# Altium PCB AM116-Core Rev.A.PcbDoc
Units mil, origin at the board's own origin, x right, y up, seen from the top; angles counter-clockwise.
Board outline 2542.62 x 1642.92 mil, 2 copper layers (Top Layer, Bottom Layer); 68 components, 59 nets, 273 pads, 217 vias.
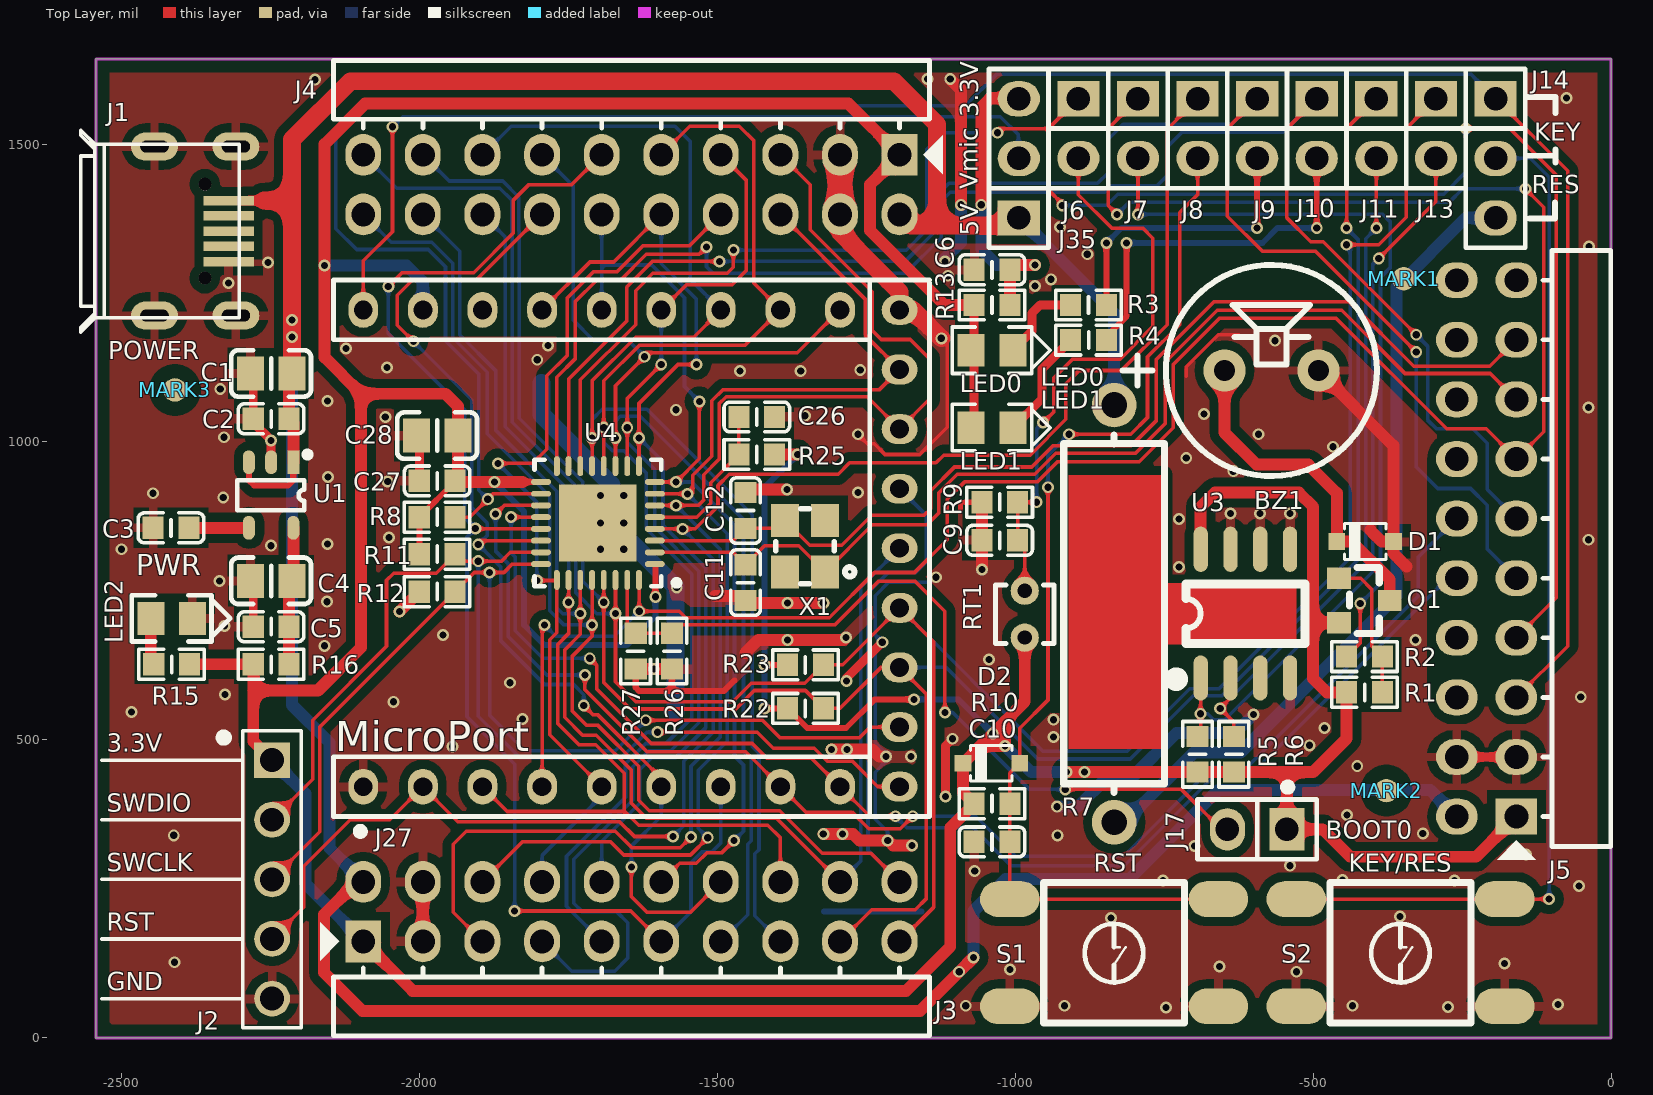
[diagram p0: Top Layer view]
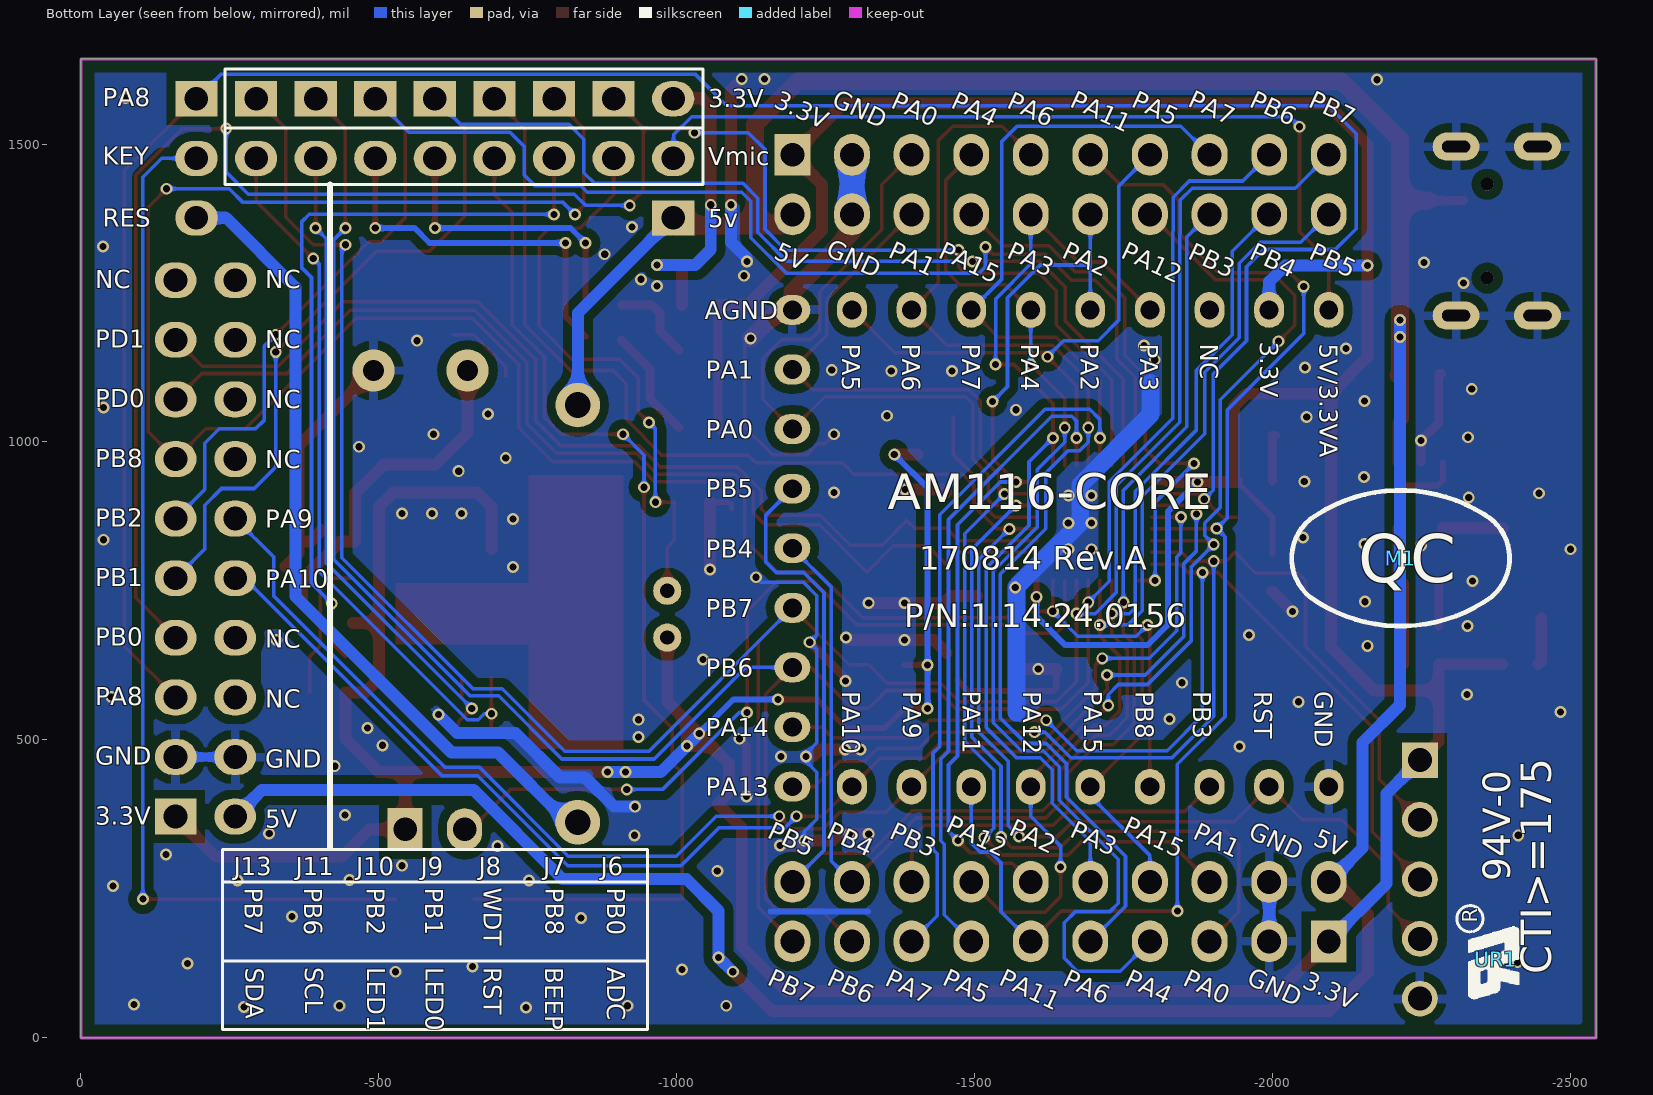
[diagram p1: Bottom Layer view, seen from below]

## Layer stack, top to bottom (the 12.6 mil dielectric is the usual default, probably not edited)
Top Solder: solder mask 0.4, Solder Resist, Dk 3.5
Top Layer: signal copper 1.4
Dielectric1: core 12.6, FR-4, Dk 4.8
Bottom Layer: signal copper 1.4
Bottom Solder: solder mask 0.4, Solder Resist, Dk 3.5

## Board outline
-2542.62,0 0,0 0,1642.92 -2542.62,1642.92

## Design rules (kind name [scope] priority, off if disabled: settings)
Clearance Clearance_Keepout [OnLayer('Keep-Out Layer')] p1: gap=20
Clearance Clearance_Manual [OnLayer('Bottom Layer') and IsSMTPin vs IsPadHoleValid>   (  HasFootprint('PAD-35/50') or   HasFootprint('HOLE-3.2') or  HasFootprint('HOLE-3.2 - Screw') or   HasFootprint('HOLE4.22-SMT') or   HasFootprint('Mou Hole-300D450W310H-SMD') or    HasFootprint('AW6748') or  HasFootprint('IDCS80P500W-20X2-F')  )] p2: gap=50
Clearance Clearance_Via2Via [IsVia vs IsVia] p3: gap=6
Clearance Clearance_Poly2All [InPoly] p4: gap=15
Clearance Clearance_TP [HasFootprint('PAD-40') vs HasFootprint('PAD-40')] p5: gap=50
Clearance [All] p6: gap=6
ComponentClearance [All] p1: gap=0 collisioncheckmode=3 verticalgap=0 showdistances=FALSE
DiffPairsRouting [All] p1: maxlimit=8 minlimit=8 mostfreqgap=8 toplayer_minwidth=5.5 toplayer_maxwidth=5.5 toplayer_prefwidth=5.5 bottomlayer_minwidth=5.5 bottomlayer_maxwidth=5.5 bottomlayer_prefwidth=5.5 maxuncoupledlength=500
HoleSize [All] p1: absolutevalues=TRUE maxlimit=1000 minlimit=1 maxpercent=80.000 minpercent=20.000
MinimumSolderMaskSliver [All] p1: minsoldermaskwidth=1
PlaneClearance PlaneClearance_Full [IsVia] p1: clearance=9
PlaneClearance [All] p2: clearance=20
PlaneConnect PlaneConnect_Full [IsVia] p1: planeconnectstyle=Direct reliefexpansion=20 reliefentries=4 reliefconductorwidth=10 reliefairgap=10
PlaneConnect [All] p2: planeconnectstyle=Relief reliefexpansion=10 reliefentries=4 reliefconductorwidth=15 reliefairgap=10
PolygonConnect PolygonConnect_SMDHole [HasFootprint('Mou Hole-300D450W310H-SMD') or HasFootprint('Mou Hole-373D600H-SMD')] p1: connectstyle=Relief reliefconductorwidth=80 reliefentries=4 polygonreliefangle="45 Angle" airgapwidth=20
PolygonConnect PolygonConnect_Full [IsVia or   HasFootprint('PAD-40') or   HasFootprint('PAD-35/50') or  HasFootprint('HOLE-3.2') or   HasFootprint('HOLE-3.2 - Screw')] p2: connectstyle=Direct reliefconductorwidth=10 reliefentries=4 polygonreliefangle="90 Angle" airgapwidth=10
PolygonConnect [All] p3: connectstyle=Relief reliefconductorwidth=15 reliefentries=4 polygonreliefangle="90 Angle" airgapwidth=15
RoutingVias [All] p1: holewidth=12 width=20 viastyle="Through Hole" minholewidth=12 minwidth=20 maxholewidth=12 maxwidth=20
SilkToSilkClearance [All] p1: silktosilkclearance=0
SilkToSolderMaskClearance [IsPad] p1: minsilkscreentomaskgap=0 clearancetoexposedcopper=TRUE
SolderMaskExpansion [All] p1: expansion=4
Width [All] p1: maxlimit=100 minlimit=6 preferedwidth=6
22 further rules are at their usual default settings.

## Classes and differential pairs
component class U_02A: C1 C2 C3 C4 C5 LED2 R15 R16 U1
component class U_03: BZ1 C9 D1 J6 J7 J9 J10 J11 J13 J14 LED0 LED1 Q1 R1 R2 R3 R4 R5 R6 R7 R8 R9 RT1 S2 U3
component class U_08: C10 C11 C12 C26 C27 C28 D2 J2 J8 J17 R10 R11 R12 R22 R23 R25 R26 R27 S1 U4 X1
component class U_05: J3 J4 J5
component class 01.Main: C6 M1 MARK1 MARK2 MARK3 R13 UR1
component class U_04: J27 J35
component class U_07: J1

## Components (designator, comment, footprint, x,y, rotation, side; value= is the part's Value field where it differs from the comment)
BZ1 "BUZZER2" BUZZ-4/9 -570,1120 r0 top locked
C1 "106" 0805C -2248.62,1115 r180 top
C2 "105" 0603C -2248.62,1039 r180 top
C3 "103" 0603C -2416.62,856 r180 top
C4 "475" 0805C -2248.62,767 r180 top
C5 "104,±10%" 0603C -2248.62,690 r180 top
C6 "4.7uF" 0603C -1039,1289 r0 top
C9 "472,±10%" 0603C -1026,834.97 r180 top
C10 "105,1μF" 0603C -1039,328.97 r180 top
C11 "22P,±5%" 0603C -1452.64,764 r270 top
C12 "22P,±5%" 0603C -1452.64,885 r90 top
C26 "4.7uF" 0603C -1433.64,1042 r0 top
C27 "104,±10%" 0603C -1970,934.78 r180 top
C28 "106" 0805C -1970,1010.78 r180 top
D1 "DIODE1" SOD-323 -412.76,832.9 r180 top
D2 "DIODE1" SOD-323 -1040,460.97 r180 top
J1 "A01SB141B1-261,MicroUSB插座" MICROUSB-5S -2529,1353.92 r270 top locked
J2 "SWD" SIP-5-2.54-R90 -2247,266.05 r90 top
J3 "HEADER 10X2" IDC-20-2.54-R90 -1644,211.92 r0 top locked
J4 "HEADER 10X2" IDC-20-2.54-R90 -1644,1431.92 r180 top locked
J5 "HEADER 10X2" IDC-20-2.54-R90 -209,821.42 r90 top locked
J6 "CON2" SIP-2-2.54 -894,1525.97 r270 top locked
J7 "CON2" SIP-2-2.54 -794,1525.97 r270 top locked
J8 "RST" SIP-2-2.54 -694,1525.98 r270 top locked
J9 "CON2" SIP-2-2.54 -594,1525.97 r270 top locked
J10 "CON2" SIP-2-2.54 -494,1525.98 r270 top locked
J11 "CON2" SIP-2-2.54 -394,1525.98 r270 top locked
J13 "CON2" SIP-2-2.54 -294,1525.98 r270 top locked
J14 "CON3" SIP-3-2.54 -194,1475.98 r270 top locked
J17 "BOOT0" SIP-2-2.54 -594,350 r180 top locked
J27 "3X7Inter" "SIP-27 2.54C" -1988.98,321.66 r90 top locked
J35 "Vol_Sel" SIP-3-2.54 -994,1475.97 r90 top locked
LED0 "LED1" LED-0805 -1039,1154 r0 top
LED1 "LED1" LED-0805 -1039,1024 r0 top
LED2 "LED1" LED-0805 -2415.62,704 r0 top
M1 "ZY QC" ZY_QC -2214.74,804.97 r180 bottom
MARK1 "MARKER" MARKER-C-1.0M -348,1274 r0 top
MARK2 "MARKER" MARKER-C-1.0M -377,415 r90 top
MARK3 "MARKER" MARKER-C-1.0M -2409.98,1087.31 r90 top
Q1 "PNP-1" SOT-23 -414,734 r0 top
R1 "10KΩ,±1%" 0603R -413.76,579.89 r180 top
R2 "1.5KΩ" 0603R -413.76,639.9 r0 top
R3 "1.5KΩ" 0603R -877,1230 r0 top
R4 "1.5KΩ" 0603R -876.9,1171 r0 top
R5 "10KΩ,±1%" 0603R -694,476 r270 top
R6 "10KΩ,±1%" 0603R -633,476 r270 top
R7 "20Ω,±5%" RESAD1778W80L1450D430P -833.95,711.9 r270 top locked
R8 "4.7KΩ" 0603R -1970,873.78 r180 top
R9 "2KΩ,±0.5%" 0603R -1026,898.97 r180 top
R10 "10kΩ" 0603R -1039,392.97 r180 top
R11 "10kΩ" 0603R -1970,811.78 r180 top
R12 "10kΩ" 0603R -1970,748.78 r0 top
R13 "10Ω" 0603R -1039,1230 r180 top
R15 "1.5kΩ" 0603R -2415.62,627 r180 top
R16 "0Ω" 0603R -2248.62,627 r180 top
R22 "10kΩ" 0603R -1352,553 r180 top
R23 "10kΩ" 0603R -1352,626 r180 top
R25 "10Ω" 0603R -1433.64,979 r0 top
R26 "10kΩ" 0603R -1576,649 r90 top
R27 "10KΩ" 0603R -1637,649 r90 top
RT1 "MF52E-103F3435FB-A(2.5MM)" RES-NTC(2.0) -984,711 r180 top
S1 "RST" KEY-6S -834,142.97 r180 top locked
S2 "SW-PB4P" KEY-6S -353.36,142.94 r180 top locked
U1 "CAT6219-330TD" SOT-23-5 -2248.62,911 r270 top
U3 "LM75B" SOIC127P600X175-8N -613.74,712.01 r90 top
U4 "MM32L061NTTR" QFN50P500X500X85-33N -1700.26,864.03 r180 top locked
UR1 "UR" ZY_UR-3X2 -2374,132 r90 bottom
X1 "12.0000MHz,±10ppm" XTAL4-3.2X2.5 -1352.64,825 r90 top

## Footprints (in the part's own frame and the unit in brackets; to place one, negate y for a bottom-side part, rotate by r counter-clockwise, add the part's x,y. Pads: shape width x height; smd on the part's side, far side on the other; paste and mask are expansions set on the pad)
0603C [mm]
  rect 0.9x0.95 smd: 1(-0.762,0) 2(0.762,0)
  silkscreen extent -1.4,-0.64 1.4,0.64, body extent -0.79,-0.38 0.81,0.42, height 0.3
0603R [mm]
  rect 0.9x0.95 smd: 1(-0.762,0) 2(0.762,0)
  silkscreen extent -1.4,-0.63 1.4,0.64, body extent -0.8,-0.4 0.8,0.4, height 0.3
0805C [mm]
  rect 1.15x1.45 smd: 1(-0.889,0) 2(0.889,0)
  silkscreen extent -1.7,-0.99 1.7,0.99, body extent -1,-0.63 1,0.63, height 0.78
BUZZ-4/9 [mm]
  round 1.8 hole 0.9: 1(-2,0) 2(2,0)
  silkscreen extent -6.35,-4.5 4.5,4.5
IDC-20-2.54-R90 [mil]
  rect 60x70 hole 40: 1(-450,-50)
  oval 60x70 hole 40: 2(-450,50) 3(-350,-50) 4(-350,50) 5(-250,-50) 6(-250,50) 7(-150,-50) 8(-150,50) 9(-50,-50) 10(-50,50) 11(50,-50) 12(50,50) 13(150,-50) 14(150,50) 15(250,-50) 16(250,50) 17(350,-50) 18(350,50) 19(450,-50) 20(450,50)
  silkscreen extent -522,-208 500,-17
KEY-6S [mil]
  oval 100x60 smd: 1(-175,90) 2(-175,-90) 3(175,-90) 4(175,90)
  silkscreen extent -118,-118 118,118, body extent -201,-122 201,122, height 268
LED-0805 [mm] "130513 缩短焊盘及丝印，和0805电阻一样LSB"
  rect 1.15x1.4 smd: 1(-0.889,0) 2(0.889,0)
  silkscreen extent -1.7,-0.99 2.49,0.99, body extent -1,-0.64 1,0.64, height 1.1
MARKER-C-1.0M [mm]
  round 1 smd paste-1.016 mask+0.5: 0(0,0)
  Top Layer pour cut-out: -1.1,0 -1.016,-0.421 -0.778,-0.778 -0.421,-1.016 0,-1.1 0,-1.1 0.421,-1.016 0.778,-0.778 1.016,-0.421 1.1,0 1.1,0 1.016,0.421 0.778,0.778 0.421,1.016 0,1.1 0,1.1 -0.421,1.016 -0.778,0.778 -1.016,0.421 -1.1,0
MICROUSB-5S [mm]
  oval 1.2x2 on Top Paste: 0(-3.6,2.15) 0(-3.6,5.62) 0(3.6,2.15) 0(3.6,5.62)
  round 0.54 hole 0.55 unplated: 0(-2,4.3) 0(2,4.3)
  rect 0.4x2.15 smd: 1(-1.3,5.31) 2(-0.65,5.31) 3(0,5.31) 4(0.65,5.31) 5(1.3,5.31)
  oval 1.2x2 hole 0.5 slot 1.2 at 90 deg: 6(-3.6,5.62) 7(3.6,5.62) 8(-3.6,2.15) 9(3.6,2.15)
  silkscreen extent -4.3,-0.99 4.3,5.77
QFN50P500X500X85-33N [mm] "QFN, 32-Leads, Body 5.00x5.00mm, Pitch 0.50mm, Thermal Pad 3.60x3.60mm, IPC Medium Density"
  oval 0.85x0.25 smd: 1(-2.425,1.75) 2(-2.425,1.25) 3(-2.425,0.75) 4(-2.425,0.25) 5(-2.425,-0.25) 6(-2.425,-0.75) 7(-2.425,-1.25) 8(-2.425,-1.75) 17(2.425,-1.75) 18(2.425,-1.25) 19(2.425,-0.75) 20(2.425,-0.25) 21(2.425,0.25) 22(2.425,0.75) 23(2.425,1.25) 24(2.425,1.75)
  oval 0.25x0.85 smd: 9(-1.75,-2.425) 10(-1.25,-2.425) 11(-0.75,-2.425) 12(-0.25,-2.425) 13(0.25,-2.425) 14(0.75,-2.425) 15(1.25,-2.425) 16(1.75,-2.425) 25(1.75,2.425) 26(1.25,2.425) 27(0.75,2.425) 28(0.25,2.425) 29(-0.25,2.425) 30(-0.75,2.425) 31(-1.25,2.425) 32(-1.75,2.425)
  rect 3.3x3.3 smd: 33(0,0)
  silkscreen extent -3.47,-2.7 2.7,2.7, body extent -2.55,-2.55 2.55,2.55, height 0.85
RES-NTC(2.0) [mm]
  round 1.2 hole 0.6: 1(0,1) 2(0,-1)
  silkscreen extent -1.25,-1.25 1.25,1.25
RESAD1778W80L1450D430P [mm]
  round 1.9 hole 1.1: 1(-8.89,0) 2(8.89,0)
  silkscreen extent -7.62,-2.15 7.62,2.15
SIP-2-2.54 [mm]
  rect 1.5x1.8 hole 1: 1(-1.27,0)
  oval 1.5x1.8 hole 1: 2(1.27,0)
  silkscreen extent -2.54,-1.27 2.54,1.27, body extent -2.54,-1.27 2.54,1.27, height 7.58
SIP-3-2.54 [mm]
  rect 1.5x1.8 hole 1: 1(-2.54,0)
  oval 1.5x1.8 hole 1: 2(0,0) 3(2.54,0)
  silkscreen extent -3.81,-1.27 3.81,1.27, body extent -3.81,-1.27 3.81,1.27, height 7.58
SIP-5-2.54-R90 [mil]
  rect 60x60 hole 40.16: 1(200,0)
  round 60 hole 40.16: 2(100,0) 3(0,0) 4(-100,0) 5(-200,0)
  silkscreen extent -249,-49 249,285
"SIP-27 2.54C" [mil]
  oval 60x50 hole 31.5: 1(100,105) 2(100,5) 3(100,-95) 4(100,-195) 5(100,-295) 6(100,-395) 7(100,-495) 8(100,-595) 9(100,-695) 19(900,-695) 20(900,-595) 21(900,-495) 22(900,-395) 23(900,-295) 24(900,-195) 25(900,-95) 26(900,5) 27(900,105)
  oval 50x60 hole 31.5: 10(100,-795) 11(200,-795) 12(300,-795) 13(400,-795) 14(500,-795) 15(600,-795) 16(700,-795) 17(800,-795) 18(900,-795)
  silkscreen extent 20,-845 950,155
SOD-323 [mil]
  rect 28x28 smd: 1(-47.5,0) 2(47.5,0)
  silkscreen extent -35,-30 35,30, body extent -51,-26 51,25, height 39
SOIC127P600X175-8N [mil]
  oval 76.06x24 smd: 1(-108.03,75) 2(-108.03,25) 3(-108.03,-25) 4(-108.03,-75) 5(108.03,-75) 6(108.03,-25) 7(108.03,25) 8(108.03,75)
  silkscreen extent -118,-100 50,124, body extent -118,-96 118,97, height 61
SOT-23 [mil]
  rect 40x36 smd: 1(-42.5,37.4) 2(-42.5,-37.4) 3(42.5,0)
  silkscreen extent -25,-55 25,56, body extent -47,-57 50,58, height 39
SOT-23-5 [mil]
  rect 40x20 smd: 1(-55,37.4)
  oval 40x20 smd: 2(-55,0) 3(-55,-37.4) 4(55,-37.4) 5(55,37.4)
  silkscreen extent -73,-57 26,66, body extent -55,-57 55,57, height 43
XTAL4-3.2X2.5 [mm] "3.2x2.5x0.75mm"
  rect 1.4x1.2 smd: 1(-1.1,-0.85) 2(1.1,-0.85) 3(1.1,0.85) 4(-1.1,0.85)
  silkscreen extent -1.6,-2.1 1.6,1.25
ZY_QC [mil]
  silkscreen extent -183,-114 183,114
ZY_UR-3X2 [mil]
  silkscreen extent -67,-40 90,65

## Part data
BZ1: library part 1.06.09.0016, "Buzzer有极性"
C1 C28: library part 1.02.02.0055, "106,10μF,±10%,10V,X5R,0805,RoHS"
C2 C10: library part 1.02.01.0036, "105,1μF,±10%,16V,X7R,0603,*,RoHS"
C3: library part 1.02.01.0024, "103,±10%,50V,X7R,0603,*,RoHS"
C4: library part 1.02.02.0064, "475,±10%,16V,X7R,0805,RoHS"
C5: library part 1.02.01.0032, "Capacitor"
C6 C26: library part 1.02.01.0080, "GRM188R61A475KE15D,4.7uF,±10%,10V,X5R,0603,muRata,RoHS"
C9: library part 1.02.01.0057, "Capacitor"
C11 C12: library part 1.02.01.0005, "22P,±5%,50V,COG,0603,*,RoHS"
C27: library part 1.02.01.0032, "104,±10%,50V,X7R,0603,*,RoHS"
D1 D2: library part 1.04.07.0027, "1N4148,SOD-323,RoHS"
J1: library part 1.10.12.0014, "A01SB141B1-261,MicroUSB插座,SMT,艾立信,RoHS"
J2: library part CON5, "Connector"
J6 J7 J9 J10 J11 J13 J14: "Connector"
J8 J17: library part CON2, "Connector"
J35: library part CON3, "Connector"
LED0 LED1: library part 1.04.05.0002, "绿色,0805,0805,RoHS"
LED2: library part 1.04.05.0001, "红色,0805,0805,RoHS"
Q1: library part 1.04.09.0002, "PNP Transistor"
R1 R5 R6 R10 R11 R12 R22 R23 R26: library part 1.01.01.0052, "10KΩ,±1%,0603,*,RoHS"
R2 R3 R4 R15: library part 1.01.01.0037, "1.5KΩ,0603,*,RoHS"
R7: library part 1.01.10.0003, "20Ω,±5%,2W,Ф5.5×16mm,RoHS"
R8: library part 1.01.01.0045, "4.7KΩ,0603,*,RoHS"
R9: library part 1.01.01.0084
R13 R25: library part 1.01.01.0007, "10Ω,0603,*,RoHS"
R16: library part 1.01.01.0001
R27: library part 1.01.01.0051, "10KΩ,0603,*,RoHS"
RT1: library part 1.01.14.0011, "MF52E-103F3435FB-A(2.5MM),THT,RoHS"
S1 S2: library part 1.09.01.0003, "6×6×5.0mm,黑色,SMD,,*"
U1: library part 1.05.10.0321, "CAT6219-330TD,TSOT-23-5,ON,RoHS"
U3: library part 1.05.10.0602, "LM75BD,SO-9,NXP,RoHS"
U4: library part 1.05.02.0199, "MM32L061NTTR,QFN32,mindmotion,RoHS"
X1: library part 1.07.01.0032, "12.0000MHz,±10ppm,10pF,-40~85℃,±10ppm,SMD3225,*,JYEG,RoHS"

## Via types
v1: diameter 20, hole 12, Top Layer to Bottom Layer, tented both sides, 217 vias

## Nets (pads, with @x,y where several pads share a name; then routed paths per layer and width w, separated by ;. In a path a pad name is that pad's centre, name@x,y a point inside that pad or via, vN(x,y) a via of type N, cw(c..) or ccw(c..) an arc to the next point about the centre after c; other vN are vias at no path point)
3.3V: C27.1 C28.1 D2.2 J2.1 J3.1 J4.1 J5.1 J17.1 J27.26 LED0.1 LED1.1 Q1.2 R1.2 R5.2 R6.2 R8.2 R10.2 R11.2 R13.2 R15.1 R16.2 R22.2 R23.2 R25.2 RT1.1 U3.8 U4.1 U4.17 | length 9438.1
  Top Layer w9: -1826.92,932.92 U4.17@-1796.72,932.92
  Top Layer w10: R11.2 R8.2 -1940,933.78 C27.1 ; -1912.36,932.92 -1910.26,935.03 ; v1(-1603.8,740.2) U4.1@-1603.8,795.13 ; v1(-1421,553) R22.2 -1349,520 -1284,520 -1236,568 v1(-1170,568) ; v1(-1421,626) R23.2
  Top Layer w15: LED1.1@-1074,1019 -1069,1024 R13.2
  Top Layer w20: R15.1 R16.2 ; R16.2 -2278.62,583 ; J2.1 -2278.62,497.67 -2278.62,583 ; J3.1 -2011.08,79 -1183,79 -1109,153 -1109,352.98 R10.2 -1087.5,411.48 D2.2 -1058.47,490 ; -1826.92,932.92 -1912.36,932.92 -1938.14,932.92 C27.1 -1935,939.78 C28.1 -1935,1060 -1956,1081 -2098,1081 ; R25.2 v1(-1365,979) ; R13.2 -1119,1230 -1244,1355 -1244,1431.92 J4.1 -1280.08,1568 -2091,1568 -2159,1500 v1(-2159,1296) -2159,1142 -2098,1081 ; RT1.1 -984,564.47 -1017,531.47 ; v1(-914,446) R5.2 R6.2 -544,446 ; U3.8 -688.74,891.26 -665,915 -524,915 -500,891 -500,696.6 ; Q1.2 -500,696.6 ; J5.1 -226.42,304 -438,304 -484,350 J17.1 -544,446 ; -2278.62,583 -2170,583 -2098,655 -2098,1081 ; -1058.47,490 v1(-1017,490) ; -1058.47,490 v1(-1037.74,510.74) ; v1(-1037.74,510.74) v1(-1017,490) ; v1(-1037.74,510.74) -1017,531.47 ; v1(-1017,490) -1017,531.47 ; -544,446 -500.24,446 -443.76,502.48 R1.2 -476.89,579.89 -500,603 -500,696.6
  Bottom Layer w10: v1(-1874,933) -1824,883 -1824,693 -1790,659 -1652,659 -1603.8,707.2 v1(-1603.8,740.2) ; v1(-1421,553) v1(-1421,626) -1421,923 v1(-1365,979) ; v1(-1170,568) -1095,568 v1(-1037.74,510.74)
  Bottom Layer w20: J2.1 -2191,410.05 -2191,258.92 J3.1 ; v1(-2159,1296) -2021,1296 -1993.98,1268.98 J27.26 ; v1(-1037.74,510.74) -973,446 v1(-914,446) v1(-883.77,446)
3.3VA: C6.2 J35.3 R13.1 | length 512.7
  Top Layer w20: v1(-1057,1398) -1057,1562 -1042,1577 J35.3@-994.62,1577 ; R13.1 C6.2 -1001,1297 v1(-967,1297)
  Bottom Layer w20: v1(-1057,1398) -1057,1323 -1031,1297 v1(-967,1297)
3.3VA_MM32L: C26.1 R25.1 U4.5 | length 267
  Top Layer w6: U4.5@-1603.8,873.87 -1534.13,873.87 -1510.76,897.24 -1510.76,931.88 R25.1 C26.1
5V: C1.1 C2.1 J1.1 J3.2 J4.2 J5.2 J35.1 R7.1 U1.1 U1.3 | length 6081.5
  Top Layer w10: U1.3 -2286.02,936.02 -2277,927 -2220,927 -2211.22,935.78 U1.1
  Top Layer w15: J1.1 -2260.9,1405.1
  Top Layer w20: C1.1 -2218.62,1110 C2.1 -2211.22,1031.6 U1.1 ; J3.2 -2105.08,261.92 -2160,207 -2160,110 -2095,45 -1160,45 v1(-1094,111) v1(-1070,135)
  Top Layer w30: -2260.9,1405.1 -2213.62,1405.1 ; C1.1@-2211.22,1112.6 C1.1 v1(-2213.62,1176) v1(-2213.62,1205) -2213.62,1405.1 ; J4.2 -1175.08,1363 -1131,1363 ; J35.1@-999.54,1381.92 -994.62,1377 -1008.62,1363 -1131,1363 ; -2213.62,1405.1 -2213.62,1507.38 -2115.58,1605.42 -1203.42,1605.42 -1131,1533 -1131,1363
  Bottom Layer w20: v1(-2213.62,1205) v1(-2213.62,1176) -2213.62,558.62 -2151,496 -2151,318.92 J3.2 ; v1(-1094,111) v1(-1070,135) -1070,213 -1016,267 -808,267 -659,416 -303.58,416 J5.2 ; J35.1@-994.62,1377 -833.95,1216.33 R7.1
5V/3.3VA_MICROP: J27.27 J35.2 | length 1444.8
  Top Layer w6: J27.27 -2093.98,1304.02 -2045,1353 v1(-2045,1529) ; J35.2@-994.62,1477 J35.2@-994.62,1485.62
  Bottom Layer w6: v1(-2045,1529) -2028,1546 -1025.13,1546 -994.62,1515.49 J35.2@-994.62,1477
ADC: C9.1 J6.2 R9.1 RT1.2 | length 971.4
  Top Layer w6: RT1.2 -984,822.97 C9.1 R9.1 v1@-965.03,898.97 ; v1(-953.5,1032.5) -935,1051 -935,1108 -904,1139 -824,1139 -769,1194 -769,1342 -786,1359 -838,1359 -894,1415 J6.2
  Bottom Layer w6: v1(-964,899) -964,1022 v1(-953.5,1032.5)
ADC0/IO19_MICROP: J3.6 J4.6 J27.17 U4.7 | length 1970.1
  Top Layer w6: J3.6 -1826.92,329 -1679,329 -1657,307 -1545,307 v1(-1516,336) ; U4.7@-1603.8,913.24 -1603.56,913 v1(-1550,913) -1542,913 -1541,914 -1541,943.95 -1509,975.95 -1509,1069 -1490,1088 -1227.64,1088 J27.17 -1252,1179.67 -1252,1239.92 J4.6
  Bottom Layer w6: v1(-1550,913) -1483,846 -1483,498 -1532,449 -1532,352 v1(-1516,336)
ADC1/IO20_MICROP: J3.5 J4.5 J27.16 U4.6 | length 2418.6
  Top Layer w6: J3.5 -1943,210.92 -1943,325 -1921,347 -1671,347 -1643,319 -1562,319 v1(-1544,337) ; U4.6@-1603.8,893.55 v1(-1569,893.55) -1531.93,893.55 -1522.76,902.72 -1522.76,945.22 -1497,970.98 -1497,1064.03 -1485.03,1076 -1248.33,1076 J27.16 -1144,1071.64 -1144,1140 -1176,1172 -1225,1172 -1240,1187 -1240,1252 -1344,1356 -1344,1431.92 J4.5
  Bottom Layer w6: v1(-1569,893.55) -1495,819.55 -1495,505 -1544,456 v1(-1544,337)
AGND: BZ1.2 C1.2 C2.2 C3.2 C4.2 C5.2 C6.1 C9.2 C10.2 C11.2 C12.2 C26.2 C27.2 C28.2 D1.1 J1.5 J1.6 J1.7 J1.8 J1.9 J2.5 J3.3 J3.4 J4.3 J4.4 J5.3 J5.4 J27.1 J27.18 LED2.2 R9.2 R12.1 R26.1 R27.1 S1.1 S1.4 S2.1 S2.4 U1.2 U3.4 U3.5 U3.6 U3.7 U4.33 | length 5610.4
  Top Layer w6: v1(-1264,1013) -1248.02,997.02 -1236.66,997.02 -1218.63,979 -1160,979 -1114.13,1024.87 -1114.13,1176.13 -1116.27,1174 v1(-1124,1174) ; -713,1110.48 -713,1126.05 -659.05,1180 -625,1180
  Top Layer w8: -1092,887 -1092,896 -1089.03,898.97 R9.2
  Top Layer w10: R27.1 -1637,588 -1631,582 -1576,582 ; R26.1 -1576,582 ; -1471,600 -1489,582 -1576,582
  Top Layer w15: C4.2 -2278.62,767 C5.2 ; C1.2 -2278.62,1115 C2.2 -2278.62,1032.62 v1(-2248.62,1002.62) U1.2 ; C28.2 -2000,1010.78 C27.2 ; v1(-1283,599) -1283,604 v1(-1223,664) ; v1(-1117,405) -1117,490 v1(-1105,502) ; J5.4 J5.3
  Top Layer w20: v1(-2033,715.78) R12.1 ; J3.3 J3.4 ; R27.1 v1(-1606.5,619) R26.1 ; -1503.5,741.5 -1460.14,741.5 C11.2 -1448.64,730 v1(-1382,730) v1(-1322,730) ; -1453,646 -1431,668 v1(-1382,668) -1288,668 v1(-1284,672) ; C12.2 -1447.64,920 v1(-1383,920) ; v1(-1322,342) v1(-1290,342) -1272,342 -1261,331 v1(-1214,331) -1213,331 -1205,323 v1(-1173,323) ; v1(-1308,484) v1(-1282,484) -1240,484 -1228,472 v1(-1217,472) ; v1(-1109,1609) -1091,1591 v1(-1091,1398) ; v1(-1056,786) R9.2 ; BZ1.2 -365.26,994.01 D1.1 ; -404,852 -384.9,832.9 D1.1 ; -343,791 -365.26,813.26 D1.1
  Top Layer w30: J4.4 -1294,1352 -1193.98,1251.98 J27.18 -1171.66,1221.66 v1(-1124,1174)
  Top Layer w40: J4.4 J4.3
  Bottom Layer w6: v1(-1214,331) -1214,346 -1235,367 -1235,446 -1217,464 v1(-1217,472) -1217,477.16 -1235,495.16 -1235,652 v1(-1223,664) -1235,676 -1235,742 -1212,765 -1141,765 v1(-1133,773)
  Bottom Layer w10: -1321,212 -1157,212
  Bottom Layer w15: J5.4 J5.3
  Bottom Layer w20: J3.3 J3.4 ; v1(-1118,1303) -1118,1308 -1091,1335 v1(-1091,1398) ; v1(-930,388) -895,388 -846,437 -804,437 -729,512 -631,512 v1(-600,543)
  Bottom Layer w30: -1795,1099 -1795,1046 -1677,928 -1677,864 -1570,757 -1570,546
  Bottom Layer w40: J4.4 J4.3
  other v1: -747,51 -274,52 -1083,54 -917,54 -434,54 -89,56 -528,111 -1009,115 -657,120 -179,125 -2411,127 -839,201 -354,204 -54,255 -752,264 -263,264 -451,265 -1068,280 -539,289 -143,308 -699,322 -2412,340 -929,340 -316,343 -443,374 -426,456 -1175,472 -1944,489 -506,491 -936,505 -481,520 -936,534 -1827,535 -2483,547 -2043,564 -51,572 -2326,576 -1848,596 -1044,635 -2159,658 -328,668 -1960,676 -2327,691 -2155,732 -1568,756 -2335,767 -725,790 -2500,820 -1696,820 -1657,820 -2249,826 -2154,829 -38,836 -2051,840 -1696,864 -1657,864 -725,871 -639,880 -589,880 -539,880 -2329,907 -1696,910 -1657,910 -2447,914 -1264,915 -2053,934 -2153,941 -634,951 -713,973 -467,992 -2328,1008 -592,1013 -2057,1042 -1353,1044 -683,1047 -1569,1054 -38,1058 -2154,1069 -2334,1089 -1462,1119 -1360,1119 -1260,1121 -2054,1125 -1802,1138 -2123,1157 -1784,1162 -564,1170 -967,1262 -2320,1267 -940,1273 -1113,1279 -2254,1301 -879,1315 -37,1328 -925,1361 -75,1577 -2175,1608 -1147,1609
BEEP: J7.2 R2.1 | length 1282.2
  Top Layer w6: v1(-794,1382) J7.2 ; R2.1 -421,662.66 v1(-421,729)
  Bottom Layer w6: v1(-794,1382) -383,1382 -371,1370 -371,1292 -387,1276 -387,763 v1(-421,729)
BOOT0: J17.2 R26.2 R27.2 U4.31 | length 1395.3
  Top Layer w6: U4.31@-1651.05,767.57 -1651.05,693.05 R27.2 R26.2 -1562,693 -1303,693 -1230,766 -1168,766 -1118,716 v1(-1118,546) ; v1(-916,417) -721,417 -654,350 J17.2
  Bottom Layer w6: v1(-1118,546) -1105,546 -976,417 v1(-916,417)
CS/GPIO7_MINIP: J3.7 J4.7 J27.22 U4.10 | length 1960.9
  Top Layer w6: U4.10@-1651.05,960.48 v1(-1651.05,1024) -1651.05,1072.95 v1(-1594,1130) ; J27.22 -1551.64,1264 -1475,1264 -1451,1288 -1451,1438.92 J4.7
  Bottom Layer w6: J3.7 -1744.08,112 -1672,112 -1650,134 -1650,193 -1669,212 -1727.11,212 -1741,225.89 -1741,300.03 -1642,399.03 -1642,454.97 -1614.97,482 -1578,482 -1531,529 -1531,783.34 -1605,857.34 -1605,953.77 -1651.05,999.81 v1(-1651.05,1024) ; v1(-1594,1130) J27.22@-1594,1221.64
CTS/IO13_MICROP: J3.14 J4.14 J27.6 U4.22 | length 1847.2
  Top Layer w6: v1(-2010,1169) -2037,1196 -2037,1246 -2011,1272 -1903.92,1272 J4.14 ; v1(-1901,828) -1894.5,834.5 U4.22@-1796.72,834.5 ; v1(-1724,558) -1708,542 -1700,542 -1593.98,435.98 J27.6 ; v1(-1644,287) -1644,237 -1618,211 -1544.92,211 J3.14
  Bottom Layer w6: v1(-2010,1169) -1912,1071 -1912,890 -1886,864 -1886,843 v1(-1901,828) -1863,790 -1863,666 -1790,593 -1741,593 -1724,576 v1(-1724,558) ; v1(-1644,287) -1644,322 -1593.98,372.02 J27.6
DAC/IO21_MICROP: J3.20 J4.20 J27.15 U4.28 | length 2617.4
  Top Layer w6: U4.28@-1710.1,767.57 -1710.1,673.9 -1743,641 -1743,548 -1720,525 -1701,525 -1632,456 -1632,399 -1614,381 -1395,381 -1324,310 -1242.08,310 J3.20
  Bottom Layer w6: J4.20 -2047.08,1335 -1979,1335 -1944,1300 -1944,1175.03 -1886,1117.03 -1886,1014 -1781.16,909.16 -1781.16,717.03 -1757.13,693 v1(-1710,693) ; J3.20 -1247,314.92 -1247,747 -1213,781 -1167,781 -1149,799 -1149,876.67 J27.15
GPIO5_J5: J5.5 J14.1 R8.1 U4.18 | length 4043.7
  Top Layer w6: R8.1 -1915.22,873.78 v1(-1885,904) -1875.76,913.24 U4.18@-1796.72,913.24 ; J14.1@-193.91,1575.98 -73,1455.07 -73,657.42 J5.5
  Bottom Layer w6: v1(-1885,904) -1900,919 -1900,1114.06 -1956,1170.06 -1956,1294 -1985,1323 -2105,1323 -2140,1358 -2140,1517 -2093,1564 -1084,1564 -1030.58,1617.42 -235.35,1617.42 J14.1@-193.91,1575.98
GPIO6_J5: J5.6
GPIO7_J5: J5.7 J6.1 U4.14 | length 3214.2
  Top Layer w6: U4.14@-1729.79,960.48 -1729.79,1104.21 -1637,1197 -1637,1254 -1608,1283 -1483,1283 -1473,1293 v1(-1473,1322) ; v1(-1030,1519) -1023.03,1525.97 -944,1525.97 ; v1(-921,1397) -921,1400 -944,1423 -944,1525.97 ; J6.1 -944,1525.97 ; v1(-244,1526) -170,1526 -92,1448 -92,738.42 J5.7
  Bottom Layer w6: v1(-1473,1322) -1183,1322 -1148,1357 -1148,1491 -1120,1519 v1(-1030,1519) ; v1(-921,1397) -847,1397 -828,1416 -281,1416 -244,1453 v1(-244,1526) ; J6.1@-904.03,1575.97 J6.1
GPIO8_J5: J5.8
GPIO8_MINIP: J3.8 J4.8 J27.5 U4.25 | length 1520.4
  Top Layer w6: v1(-1868,964) -1810,964 -1786,988 -1786,1111 -1752,1145 -1752,1241 -1707,1286 -1668,1286 -1625,1329 -1546.92,1329 J4.8 ; v1(-1802.57,767.57) -1769.16,767.57 -1769.16,679.84 -1781,668 -1781,508.67 J27.5
  Bottom Layer w6: v1(-1868,964) -1802.57,898.57 v1(-1802.57,767.57) ; J3.8 -1794,306 -1693.98,406.02 J27.5
GPIO9_J5: J5.9 J9.1 U4.15 | length 2705.5
  Top Layer w6: U4.15@-1749.47,960.48 -1749.47,1105.53 -1652,1203 -1652,1260 -1609,1303 v1(-1496,1303) ; J9.1 -644,1525.97 -644,1379 -585,1320 -496,1320 v1(-327,1151)
  Bottom Layer w6: v1(-1496,1303) -1185.03,1303 -1136,1352.03 -1136,1409 -1111,1434 -862,1434 -844,1452 -844,1508 -819,1533 -636.97,1533 J9.1 ; v1(-327,1151) -327,958 -291,922 -236,922 -208,894 -208,820.42 J5.9
GPIO10_J5: J5.10 J27.9 U4.20 | length 2209.7
  Top Layer w6: v1(-1846,874) -1796.85,874 U4.20@-1796.72,873.87 ; v1(-1714,637) -1702.42,625.42 -1702.42,585.42 -1611,494 -1441,494 -1416,469 -1341.33,469 J27.9 -1244.33,372 v1(-1201,372)
  Bottom Layer w6: v1(-1846,874) -1846,814 -1839,807 -1839,683 -1793,637 v1(-1714,637) ; v1(-1201,372) -1182,353 -1071,353 -1007,289 -817,289 -666,440 -606,440 -274.58,771.42 J5.10
GPIO11_J5: J5.11 J10.1 U4.16 | length 2725.7
  Top Layer w6: U4.16@-1769.16,960.48 -1769.16,1108.84 -1738,1140 -1738,1236 -1702.34,1271.66 -1662.34,1271.66 -1619,1315 -1530,1315 v1(-1518,1327) ; J10.1 -544,1525.98 -544,1376 -504,1336 -483,1336 v1(-327,1180)
  Bottom Layer w6: v1(-1518,1327) -1518,1294 -1507,1283 -1184,1283 -1124,1343 -1124,1404.03 -1109.03,1419 -850,1419 -839,1430 -762,1430 -744,1448 -744,1496 -720,1520 -549.98,1520 J10.1 ; v1(-327,1180) -308,1161 -308,1037 -293,1022 -232,1022 -208,998 -208,920.42 J5.11
GPIO11_MINIP: J3.11 J4.11 J27.7 U4.21 | length 2317.1
  Top Layer w6: v1(-2052,1261) -2029,1284 -1908.89,1284 -1842,1350.89 -1842,1405.97 -1815.97,1432 -1743.92,1432 J4.11 ; v1(-1906,855) -1905.18,854.18 U4.21@-1796.72,854.18 ; v1(-1840,213) -1645.08,213 J3.11
  Bottom Layer w6: v1(-2052,1261) -2052,1182 -1924,1054 -1924,873 v1(-1906,855) -1920,841 -1920,539 -1840,459 v1(-1840,213) ; J3.11 -1544,211.92 -1544,294 -1526,312 -1509,312 -1493.98,327.02 J27.7
GPIO12_J5: J5.12 J27.8 U4.19 | length 2344.8
  Top Layer w6: v1(-1872,879) -1857.44,893.56 U4.19@-1796.72,893.56 ; v1(-1722,609) -1722,584 -1618,480 -1452.33,480 J27.8 -1351.33,379 -1274,379 -1246,351 -1193,351 v1(-1172,372)
  Bottom Layer w6: v1(-1872,879) -1872,817 -1851,796 -1851,674 -1786,609 v1(-1722,609) ; v1(-1172,372) -1066.03,372 -999.03,305 -817.97,305 -668.97,454 -611,454 -324,741 -324,806.42 J5.12
GPIO13_J5: J5.13 J7.1 J27.4 U4.32 | length 3803
  Top Layer w6: J27.4 -1793.98,689.02 v1(-1790,693) ; U4.32@-1631.36,767.57 -1631,767.21 v1(-1631,716) -1563.85,716 -1552.85,705 -1312,705 -1236,781 -1169,781 -1114,836 -1114,904 -1085,933 -963.06,933 -929.06,967 -792,967 -735,1024 -735,1130 -657,1208 -462,1208 -276,1022 -209.58,1022 J5.13 -113,1017.42 -113,1394.09 v1(-143.91,1425) ; v1(-829,1382) -844,1397 -844,1525.97 J7.1
  Bottom Layer w6: v1(-1790,693) -1771,674 -1673,674 v1(-1631,716) ; v1(-829,1382) -809,1402 -272,1402 -249,1425 v1(-143.91,1425)
GPIO14_J5: J5.14
GPIO15_J5: C11.1 J5.15 U4.2 X1.1 | length 1809.2
  Top Layer w6: U4.2@-1603.8,814.81 -1473.45,814.81 C11.1 -1420.64,826 -1363.48,826 X1.1 -1239.87,861 -1148,861 -1128,881 -1128,915 -1097,946 -967.03,946 -932.03,981 -798,981 -748,1031 -748,1134 -661,1221 -452,1221 -346,1115 -202.58,1115 J5.15
GPIO16_J5: J5.16
GPIO16_MINIP: J3.16 J4.16 J27.3 U4.26 | length 1778.9
  Top Layer w6: J27.3 -1852.33,380 -1655,380 ; U4.26@-1749.47,767.57 v1(-1749.47,731) -1749.47,678.53 -1768,660 -1768,528 -1732,492 -1703.85,492 -1656,444.15 -1656,381 -1655,380 ; J3.16 -1394,336 -1415,357 -1632,357 -1655,380
  Bottom Layer w6: J4.16 -1856,1343.92 -1856,1025.4 -1749.47,918.88 v1(-1749.47,731)
GPIO17_J5: C12.1 J5.17 U4.3 X1.3 | length 1786
  Top Layer w6: U4.3@-1603.8,834.5 -1473.14,834.5 C12.1 -1399.41,855 X1.3 -1344.8,827 -1290.84,827 -1240.84,877 -1153,877 -1142,888 -1142,918 -1102,958 -972,958 -936,994 -805,994 -763,1036 -763,1139 -667,1235 -439,1235 -331,1127 -203.42,1127 J5.17
GPIO18_J5: J5.18
GPIO18_MINIP: J3.18 J4.18 J27.14 U4.27 | length 2246.8
  Top Layer w6: U4.27@-1729.79,767.57 v1(-1729.79,712) -1729.79,677.21 -1756,651 -1756,538 -1726,508 -1702.88,508 -1644,449.12 -1644,394 -1619,369 -1401.08,369 J3.18
  Bottom Layer w6: J4.18 -1932,1319.92 -1932,1180 -1872,1120 -1872,1020 -1769.16,917.16 -1769.16,722 -1759.16,712 v1(-1729.79,712) ; J3.18 -1259,296.92 -1259,756.64 J27.14
GPIO19_J5: J5.19
GPIO20_J5: J5.20
"IO 1_MICROP": J3.12 J4.12 J27.23 U4.8 | length 1513.6
  Top Layer w6: U4.8@-1603.8,932.92 v1(-1569,932.92) -1530,971.92 v1(-1530,1068) ; J3.12 -1562.92,293 -1535,293 -1517,311 -1492,311 v1(-1472,331)
  Bottom Layer w6: J27.23 -1693.98,1297 ; J4.12@-1693.98,1381.9 -1693.98,1297 ; v1(-1569,932.92) -1543.05,932.92 -1471,860.87 -1471,473.06 -1456,458.06 -1456,347 v1(-1472,331) ; v1(-1530,1068) -1555,1093 -1555,1242 -1610,1297 -1693.98,1297
"IO 2_MICROP": J2.3 J27.11 R12.2 U4.24 | length 1765.3
  Top Layer w6: J2.3 -2167,346.05 -2167,521.78 R12.2 -1907.78,781 v1(-1882,781) -1858,781 -1843.87,795.13 U4.24@-1796.72,795.13 ; v1(-1620,533) -1424,533 -1395,504 -1261,504 -1243.34,521.66 J27.11
  Bottom Layer w6: v1(-1882,781) -1882,540.97 -1823.03,482 -1671,482 v1(-1620,533)
"IO 3_MICROP": J2.2 J27.10 R11.1 U4.23 | length 1823.2
  Top Layer w6: J2.2 -2179,434.05 -2179,533 -2055,657 -2055,768 -2043,780 -1971.78,780 R11.1 -1936.78,815 -1921.78,800 v1(-1901,800) -1862,800 -1847.19,814.81 U4.23@-1796.72,814.81 ; v1(-1600,513) -1433,513 -1406,486 -1337,486 -1315,464 -1273,464 -1230.66,421.66 J27.10
  Bottom Layer w6: v1(-1901,800) -1901,540 -1831,470 -1660.91,470 -1617.91,513 v1(-1600,513)
LED0: J9.2 R3.2 | length 478.6
  Top Layer w10: R3.2@-847.38,1235.89 -847,1236.27 v1(-847,1334) ; v1(-594,1359) J9.2
  Bottom Layer w10: v1(-847,1334) -846.7,1334 -821.7,1359 v1(-594,1359)
LED1: J10.2 R4.2 | length 617.6
  Top Layer w10: R4.2@-847.28,1176.89 -813,1211.18 v1(-813,1334) ; v1(-494,1359) J10.2
  Bottom Layer w10: v1(-813,1334) -585,1334 -560,1359 v1(-494,1359)
LM75_SCL: J3.17 J4.17 J11.1 J27.12 R22.1 U4.29 | length 4024.6
  Top Layer w6: U4.29@-1690.42,767.57 v1(-1690.42,731) -1690.42,596.42 -1646,552 -1469,552 -1438,583 -1352,583 R22.1 -1294,553 -1225.34,621.66 J27.12 -1149,576.67 -1149,234 -1168,215 -1240.92,215 J3.17 ; v1(-444,1359) -444,1525.98 J11.1
  Bottom Layer w6: J4.17 -1950,1437.92 -1859.95,1437.92 -1833,1410.97 -1833,1354.86 -1832,1353.86 -1832,1040 -1725.47,933.47 -1725.47,766.06 v1(-1690.42,731) ; J27.12 -1115.66,621.66 -962,468 -807,468 -701,574 -653.03,574 -424,803.03 -424,1339 v1(-444,1359)
LM75_SDA: J3.19 J4.19 J13.1 J27.13 R23.1 U4.30 | length 4254.3
  Top Layer w6: U4.30@-1670.73,767.57 v1(-1670.73,712) -1670.73,597.73 -1637,564 -1473.97,564 -1442.97,595 -1353,595 R23.1 -1289.64,626 J27.13 -1137,664.67 -1137,218.92 J3.19 ; v1(-444,1331) -390,1331 -344,1377 -344,1525.98 J13.1
  Bottom Layer w6: J4.19 -2038,1425.92 -1864.92,1425.92 -1845,1406 -1845,1349.89 -1844,1348.89 -1844,1033 -1737.47,926.47 -1737.47,747.37 -1702.1,712 v1(-1670.73,712) ; J27.13 -953.33,481 -812,481 -707,586 -658,586 -438,806 -438,1325 v1(-444,1331)
MISO/GPIO9_MINIP: J3.9 J4.9 J27.20 U4.12 | length 2041.7
  Top Layer w6: U4.12@-1690.42,960.48 v1(-1690.42,1024) -1690.42,1102.58 -1631,1162 -1453.64,1162 J27.20 -1439,1266.67 -1439,1506 -1463,1530 -1545.92,1530 J4.9
  Bottom Layer w6: J3.9 -1753,220.92 -1753,305 -1654,404 -1654,459.94 -1619.94,494 -1585.91,494 -1543,536.91 -1543,778.37 -1619,854.37 -1619,948 -1656,985 -1675.6,985 -1690.42,999.81 v1(-1690.42,1024)
MOSI/GPIO15_MINIP: J3.15 J4.15 J27.21 U4.13 | length 2212.6
  Top Layer w6: U4.13@-1710.1,960.48 v1(-1710.1,1007) -1710.1,1102.9 -1637,1176 -1539.64,1176 J27.21
  Bottom Layer w6: J4.15 -1845.92,1530 -1571,1530 -1545,1504 -1545,1272.67 J27.21 ; v1(-1710.1,1007) -1710.1,1037.9 -1693,1055 -1618,1055 -1441,878 -1441,489 -1430,478 -1430,316 -1437,309 -1437,204.92 J3.15
NetBZ1_1: BZ1.1 D1.2 Q1.3 | length 566.6
  Top Layer w20: BZ1.1 -648.74,1015.74 -595,962 -508,962 -460.26,914.26 D1.2 -435,832.9 -371.5,769.4 Q1.3
NetC3_1: C3.1 U1.4 | length 100.6
  Top Layer w20: C3.1 U1.4
NetC4_1: C4.1 C5.1 R16.1 U1.5 | length 232.1
  Top Layer w20: R16.1 C5.1 -2218.62,762 C4.1 -2211.22,769.4 U1.5
NetC10_1: C10.1 D2.1 J8.2 R10.1 S1.2 S1.3 | length 1784.4
  Top Layer w6: v1(-945,924) -945,567 -992.5,519.5 D2.1 -1009,444.47 R10.1 C10.1 S1.3 S1.2 ; v1(-910,1013) -806,1013 -778,1041 -778,1143 -724,1197 -724,1385 -694,1415 J8.2
  Bottom Layer w6: v1(-945,924) -945,978 v1(-910,1013)
NetJ14_2: J14.2 S2.2 S2.3 | length 1738.5
  Top Layer w6: S2.3 S2.2 v1(-104,233) v1(-104,233)
  Bottom Layer w6: J14.2@-193.91,1475.98 -135.98,1475.98 -104,1444 v1(-104,233)
NetJ14_3: J14.3 R7.2 | length 1364.1
  Bottom Layer w20: R7.2 -817.1,361.9 -700,479 -622,479 -360,741 -360,1260 -244.02,1375.98 J14.3 J14.3@-193.91,1375.98
NetLED0_2: LED0.2 R3.1 | length 146.1
  Top Layer w15: LED0.2 -972,1186 -972,1216 -958,1230 R3.1
NetLED1_2: LED1.2 R4.1 | length 187.2
  Top Layer w15: LED1.2 -955,1073 -955,1122.9 R4.1
NetLED2_1: LED2.1 R15.2 | length 79.1
  Top Layer w20: LED2.1 -2450.62,632 R15.2
NetQ1_1: Q1.1 R1.1 R2.2 | length 242.8
  Top Layer w6: Q1.1 -420.4,771.4 -402,753 -402,658.13 R2.2 R1.1
PA3/UART2_RX: J3.10 J4.10 J27.24 U4.9 | length 1657.9
  Top Layer w6: J27.24 -1713.64,1302 -1673.92,1302 J4.10 ; U4.9@-1631.36,960.48 v1(-1631.36,1007) -1631.36,1064.64 -1566,1130 v1(-1535,1130)
  Bottom Layer w6: J3.10 -1694,330.06 -1630,394.06 -1630,450 -1610,470 -1570,470 -1519,521 -1519,788.31 -1591,860.31 -1591,966.64 v1(-1631.36,1007) ; J4.10 -1594,1299 -1535,1240 v1(-1535,1130)
PA5/SPI1_SCK: J3.13 J4.13 J27.19 U4.11 | length 2059.9
  Top Layer w6: U4.11@-1670.73,960.48 v1(-1670.73,1007) -1670.73,1094.27 v1(-1622,1143) -1615,1150 -1365.64,1150 J27.19
  Bottom Layer w6: J4.13 -1742,1429.92 -1742,1205 -1707,1170 -1649,1170 v1(-1622,1143) ; v1(-1670.73,1007) -1670.73,1035.27 -1663,1043 -1629,1043 -1456,870 -1456,481 -1443,468 -1443,331 -1449,325 -1449,206.92 J3.13
PWM2/IO7_MICROP: J27.25
R\E\S\E\T\: J2.4 J8.1 J27.2 U4.4 | length 2875.3
  Top Layer w6: J2.4 -2194,219.05 -2194,288 -2116,366 -2049.64,366 J27.2 -1935.33,363 -1664,363 -1639,338 v1(-1574,338) ; U4.4@-1603.8,854.18 v1(-1558,854.18) -1536.85,854.18 -1498.76,892.27 -1498.76,926.91 -1479.67,946 -1297,946 -1278,965 -1133,965 -1120,978 -975,978 -915,1038 -915,1098 -893,1120 -822,1120 -745,1197 -745,1524.98 J8.1
  Bottom Layer w6: v1(-1574,338) -1556,356 -1556,464 -1507,513 -1507,803.18 v1(-1558,854.18)
SCL: J11.2 R6.1 U3.2 | length 1145.8
  Top Layer w6: U3.2@-639,603.72 -639,570 v1(-656,553) -633,530 R6.1 ; v1(-394,1359) J11.2
  Bottom Layer w6: v1(-656,553) -412,797 -412,1341 v1(-394,1359)
SDA: J13.2 R5.1 U3.1 | length 1233.8
  Top Layer w6: R5.1 -689,511 v1(-689,544) -689,603.72 U3.1 ; v1(-390,1308) -294,1404 J13.2
  Bottom Layer w6: v1(-689,544) -677,544 -667,534 -648.13,534 -400,782.13 -400,1298 v1(-390,1308)
pads on no net: J1.0 J1.2 J1.3 J1.4 MARK1.0 MARK2.0 MARK3.0 U3.3 X1.2 X1.4

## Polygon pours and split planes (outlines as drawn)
AGND on Top Layer "AGND_L01_P1002" (solid, remove dead copper, pour order 1002): -2542.62,0 -2542.62,1642.92 -2227,1642.92 0,1642.92 0,0 -2542.67,0
AGND on Bottom Layer "AGND_L02_P1004" (solid, remove dead copper, pour order 1004): -2542.57,0 -2542.57,1642.92 -2226.95,1642.92 0.05,1642.92 0.05,0 -2542.62,0

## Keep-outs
Keep-Out Layer:
  the board outline again, w5

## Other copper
Top Layer:
  rectangle: -757.74,659.97 -527.74,762.97
  rectangle: -910.95,484.9 -750.95,944.9
  pour cut-out: -2292,421.05 -2292,166.05 -2201.61,166.05 -2201.61,421.05
  pour cut-out: -1988,1176.31 -1988,1253.65 -1770.35,1253.65 -1770.35,1176.31
  pour cut-out: -1939.39,104 -1894,104 -1894,161.92 -1939.39,161.92
  pour cut-out: -1111.64,1136.56 -1111.64,1069.35 -1116.63,1069.35 -1116.63,1136.56
  pour cut-out: -406.5,804.4 -406.5,767 -431.01,767 -431.01,804.4
  pour cut-out: -309.39,971.42 -309.39,571.42 -110.35,571.42 -110.35,971.42
  pour cut-out: -938.02,545 -938.02,554 -926.25,554 -926.25,545
Bottom Layer:
  pour cut-out: -1394,111.53 -1894,111.53 -1894,261.92 -1394,261.92
  pour cut-out: -2292,421.05 -2292,166.05 -2201.61,166.05 -2201.61,420 -2290,420
  pour cut-out: -1339,1338 -1246,1338 -1246,1531 -1339,1531
  pour cut-out: -601,565 -584,548 -579,548 -578,549 -578,567 -584,573 -597,573 -601,569
  pour cut-out: -303,686 -303,571.42 -122,571.42 -122,755.94 -341,755.94 -341,686

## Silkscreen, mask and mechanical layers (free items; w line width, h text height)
Top Overlay:
  lines w10: -141.74,1578.74 -93.51,1578.74 -93.51,1552.17 ; -140.76,1480.32 -93.51,1480.32 ; -136.82,1375 -95.48,1375 ; -94.5,1375 -94.5,1402 ; -93,1469 -93,1491
  text "3.3V" at -1062,1545 h30 r90
  text "KEY" at -128.94,1505.91 h30
  text "Vmic" at -1063,1424 h30 r90
  text "RES" at -132.88,1417.32 h30
  text "5V" at -1062,1346 h30 r90
  text "POWER" at -2522,1139 h30
  text "LED0" at -1093,1073 h50
  text "LED1" at -1093,943 h50
  text "PWR" at -2474.62,765 h60
  text "MicroPort" at -2140.76,481.3 h50
  text "3.3V" at -2524.58,479.92 h30
  text "SWDIO" at -2524.58,379.87 h30
  text "BOOT0" at -479,334 h30
  text "SWCLK" at -2524.58,279.83 h30
  text "RST" at -868,279 h30
  text "KEY/RES" at -440,279 h30
  text "RST" at -2524.58,179.78 h30
  text "GND" at -2524.58,79.73 h30
Bottom Overlay:
  lines w5: -1041.15,1527.24 -245.15,1527.24 ; -951,261.49 -238,261.49 ; -950,128.88 -238,128.88 ; -1044.1,1431.91 -242.15,1431.91 -242.15,1625.91 -1044.1,1625.91 -1044.1,1431.91 ; -951,13.78 -951,315.92 -238,315.92 -238,13.78 -951,13.78
  lines w10: -418.33,320 -418.33,1431.92
  text "GND" at -1258,1565 h30 r25
  text "PA7" at -1856,1564 h30 r25
  text "PB7" at -2058,1563 h30 r25
  text "PB6" at -1959,1563 h30 r25
  text "PA5" at -1761,1563 h30 r25
  text "PA11" at -1658,1563 h30 r25
  text "3.3V" at -1161,1563 h30 r25
  text "PA8" at -37,1563 h30
  text "PA6" at -1552,1562 h30 r25
  text "PA4" at -1458,1562 h30 r25
  text "PA0" at -1357,1562 h30 r25
  text "3.3V" at -1053,1562 h30
  text "KEY" at -37,1465 h30
  text "Vmic" at -1053,1464 h30
  text "RES" at -37,1361 h30
  text "5v" at -1053,1360 h30
  text "GND" at -1248,1314 h30 r25
  text "PA1" at -1353,1311 h30 r25
  text "PA12" at -1743,1310 h30 r25
  text "PA2" at -1644,1310 h30 r25
  text "PA3" at -1552,1310 h30 r25
  text "PA15" at -1437,1310 h30 r25
  text "5V" at -1161,1309 h30 r25
  text "PB5" at -2059,1308 h30 r25
  text "PB4" at -1959,1308 h30 r25
  text "PB3" at -1856,1308 h30 r25
  text "NC" at -309,1258 h30
  text "NC" at -24,1258 h30
  text "AGND" at -1047,1206 h30
  text "3.3V" at -1979,1168 h30 r90
  text "5V/3.3VA" at -2079,1165 h30 r90
  text "NC" at -1878,1165 h30 r90
  text "PA3" at -1778,1165 h30 r90
  text "PA2" at -1678,1165 h30 r90
  text "PA4" at -1578,1165 h30 r90
  text "PA7" at -1479,1165 h30 r90
  text "PA6" at -1378,1165 h30 r90
  text "PA5" at -1278,1165 h30 r90
  text "PD1" at -24,1158 h30
  text "NC" at -309,1157.44 h30
  text "PA1" at -1049,1106 h30
  text "PD0" at -24,1058 h30
  text "NC" at -309,1056.89 h30
  text "PA0" at -1049,1006 h30
  text "PB8" at -24,958 h30
  text "NC" at -309,956.33 h30
  text "PB5" at -1049,907 h30
  text "AM116-CORE" at -1353.74,886.97 h60
  text "PB2" at -24,858 h30
  text "PA9" at -309,855.78 h30
  text "PB4" at -1049,806 h30
  text "170814 Rev.A" at -1406.74,785.97 h40
  text "PB1" at -24,758 h30
  text "PA10" at -309,755.22 h30
  text "PB7" at -1049,706 h30
  text "P/N:1.14.24.0156" at -1381.74,688.97 h40
  text "PB0" at -24,658 h30
  text "NC" at -309,654.67 h30
  text "PB6" at -1049,606 h30
  text "GND" at -2070.97,582.01 h30 r90
  text "RST" at -1968.97,582.01 h30 r90
  text "PB3" at -1866.97,582.01 h30 r90
  text "PB8" at -1769.97,582.01 h30 r90
  text "PA15" at -1683.49,582.21 h30 r90
  text "PA12" at -1581,582 h30 r90
  text "PA11" at -1479.49,582.21 h30 r90
  text "PA9" at -1380,582 h30 r90
  text "PA10" at -1278,582 h30 r90
  text "PA8" at -24,558 h30
  text "NC" at -309,554.11 h30
  text "PA14" at -1049,506 h30
  text "GND" at -24,458 h30
  text "GND" at -309,453.56 h30
  text "PA13" at -1048.79,406.62 h30
  text "3.3V" at -24,358 h30
  text "5V" at -309,353 h30
  text "PA12" at -1450,348 h30 r25
  text "PA15" at -1747,346 h30 r25
  text "PA2" at -1555,342 h30 r25
  text "PA3" at -1658,338 h30 r25
  text "GND" at -1957,337 h30 r25
  text "PB4" at -1249,337 h30 r25
  text "PB5" at -1150,337 h30 r25
  text "PB3" at -1355,336 h30 r25
  text "PA1" at -1864,335 h30 r25
  text "5V" at -2066,325 h30 r25
  text "J6" at -872.06,273.21 h30
  text "J7" at -776,273 h30
  text "J8" at -668,273 h30
  text "J9" at -569.98,273.21 h30
  text "J10" at -461.8,273.21 h30
  text "J11" at -361,273 h30
  text "J13" at -256.13,273.21 h30
  text "PB0" at -883.48,252.26 h30 r90
  text "PB8" at -779.74,252.26 h30 r90
  text "WDT" at -676.01,252.26 h30 r90
  text "PB1" at -578.27,252.26 h30 r90
  text "PB2" at -479.53,252.26 h30 r90
  text "PB6" at -374.8,252.26 h30 r90
  text "PB7" at -275.06,252.26 h30 r90
  text "ADC" at -882.92,118.84 h30 r90
  text "BEEP" at -779.61,118.86 h30 r90
  text "RST" at -676.31,118.86 h30 r90
  text "LED0" at -579,118.86 h30 r90
  text "LED1" at -480.69,118.86 h30 r90
  text "SCL" at -376.39,118.86 h30 r90
  text "SDA" at -277.08,117.88 h30 r90
  text "GND" at -1955,92 h30 r25
  text "PA11" at -1539,90 h30 r25
  text "PA5" at -1444,90 h30 r25
  text "PB6" at -1250,90 h30 r25
  text "PB7" at -1150,90 h30 r25
  text "PA0" at -1847,89 h30 r25
  text "PA4" at -1750,89 h30 r25
  text "PA6" at -1646,89 h30 r25
  text "PA7" at -1347,89 h30 r25
  text "3.3V" at -2048,86 h30 r25
Mechanical 1:
  the board outline again, w5
Mechanical 15:
  region: -2134,161.92 -2166.5,194.42 -2166.5,129.42
  region: -1154,1481.92 -1121.5,1449.41 -1121.5,1514.42
  region: -159,331.42 -191.5,298.92 -126.5,298.92
  lines w8: -2094,-232.57 -2094,3.65 ; -2094,102.08 -2094,117.43 ; -2094,1526.4 -2094,1541.76 ; -2094,1640.18 -2094,1876.4 ; -1994,-232.57 -1994,3.65 ; -1994,102.08 -1994,117.43 ; -1994,1526.4 -1994,1541.76 ; -1994,1640.18 -1994,1876.4 ; -1894,-232.57 -1894,3.65 ; -1894,102.08 -1894,117.43 ; -1894,1526.4 -1894,1541.76 ; -1894,1640.18 -1894,1876.4 ; -1794,-232.57 -1794,3.65 ; -1794,102.08 -1794,117.43 ; -1794,1526.4 -1794,1541.76 ; -1794,1640.18 -1794,1876.4 ; -1694,-232.57 -1694,3.65 ; -1694,102.08 -1694,117.43 ; -1694,1526.4 -1694,1541.76 ; -1694,1640.18 -1694,1876.4 ; -1594,-232.57 -1594,3.65 ; -1594,102.08 -1594,117.43 ; -1594,1526.4 -1594,1541.76 ; -1594,1640.18 -1594,1876.4 ; -1494,-232.57 -1494,3.65 ; -1494,102.08 -1494,117.43 ; -1494,1526.4 -1494,1541.76 ; -1494,1640.18 -1494,1876.4 ; -1394,-232.57 -1394,3.65 ; -1394,102.08 -1394,117.43 ; -1394,1526.4 -1394,1541.76 ; -1394,1640.18 -1394,1876.4 ; -1294,-232.57 -1294,3.65 ; -1294,102.08 -1294,117.43 ; -1294,1526.4 -1294,1541.76 ; -1294,1640.18 -1294,1876.4 ; -1194,-232.57 -1194,3.65 ; -1194,102.08 -1194,117.43 ; -1194,1526.4 -1194,1541.76 ; -1194,1640.18 -1194,1876.4 ; -114.51,371.42 -99.16,371.42 ; -114.51,471.42 -99.16,471.42 ; -114.51,571.42 -99.16,571.42 ; -114.51,671.42 -99.16,671.42 ; -114.51,771.42 -99.16,771.42 ; -114.51,871.42 -99.16,871.42 ; -114.51,971.42 -99.16,971.42 ; -114.51,1071.42 -99.16,1071.42 ; -114.51,1171.42 -99.16,1171.42 ; -114.51,1271.42 -99.16,1271.42 ; -99.24,1321.42 -0.81,1321.42 ; -99.16,1321.42 -99.16,321.42 -0.73,321.42 -0.73,1321.42 ; -0.73,371.42 235.49,371.42 ; -0.73,471.42 235.49,471.42 ; -0.73,571.42 235.49,571.42 ; -0.73,671.42 235.49,671.42 ; -0.73,771.42 235.49,771.42 ; -0.73,871.42 235.49,871.42 ; -0.73,971.42 235.49,971.42 ; -0.73,1071.42 235.49,1071.42 ; -0.73,1171.42 235.49,1171.42 ; -0.73,1271.42 235.49,1271.42 ; -2144,3.65 -1144,3.65 -1144,102.08 -2144,102.08 -2144,3.65 ; -2144,1541.76 -1144,1541.76 -1144,1640.18 -2144,1640.18 -2144,1541.76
